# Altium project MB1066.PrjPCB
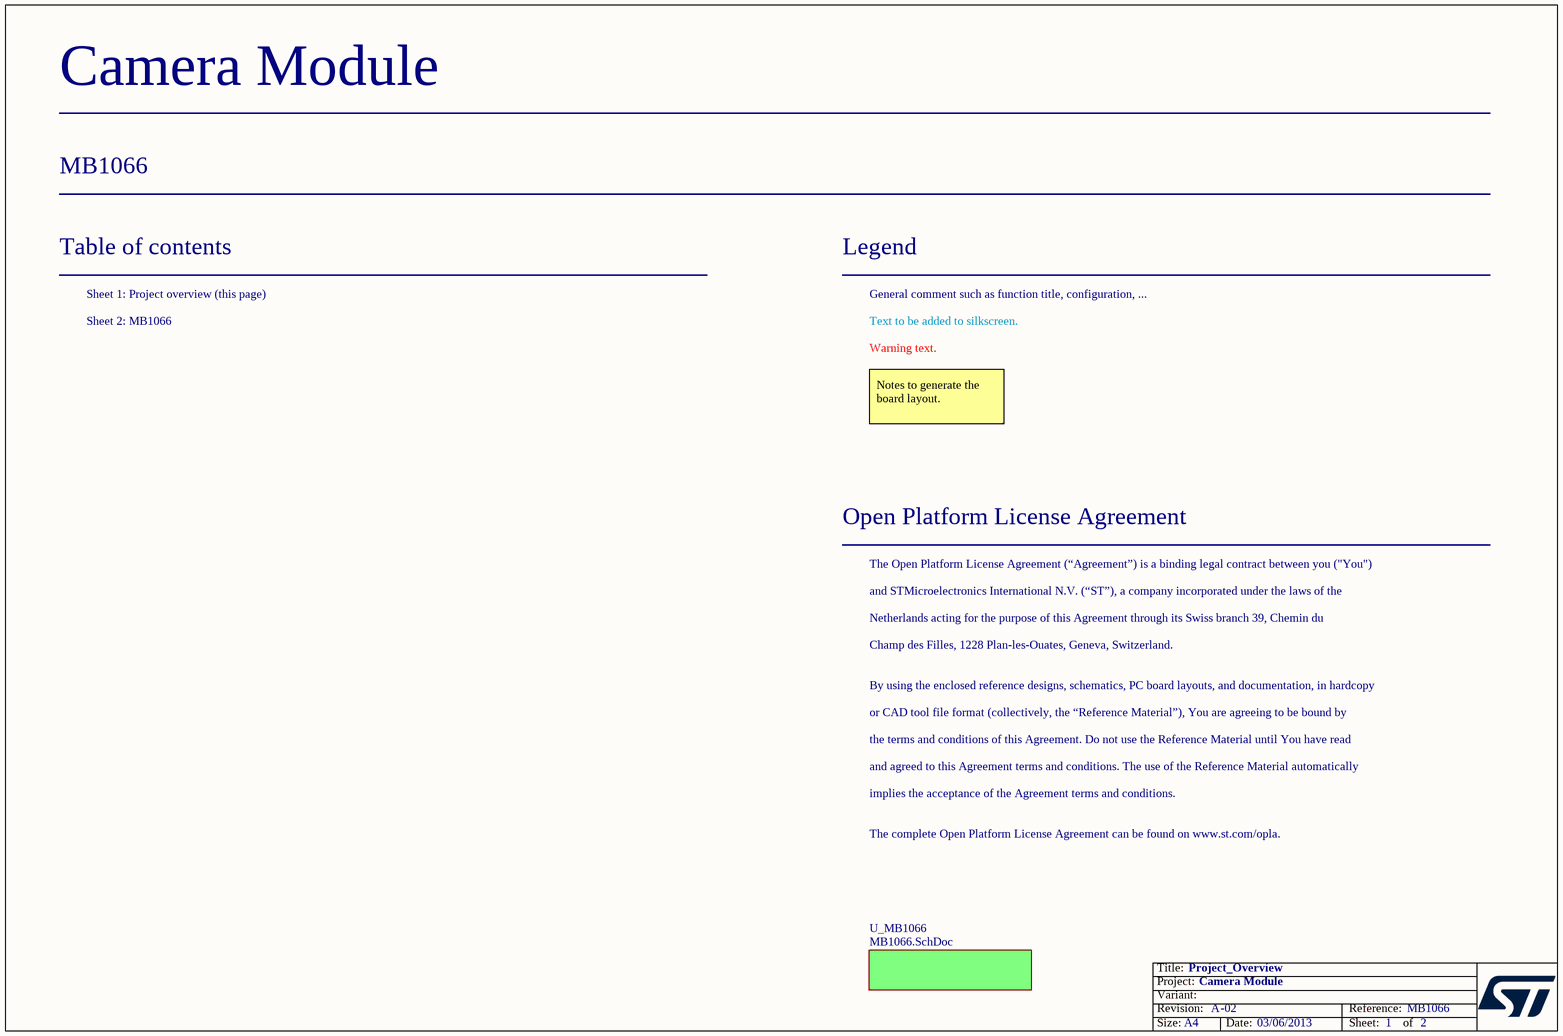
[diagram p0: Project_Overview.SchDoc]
Board_Assembly_Revision: 02; Board_Document_Date: 03/06/2013; Board_Name: Camera Module; Board_PCB_Revision: A; Board_Reference: MB1066
2 sheets, 22 parts. Net scope: global (net labels, ports and power ports of the same name join across sheets).
Board file: MB1066.PcbDoc
Sheets:
  Project_Overview.SchDoc
    U_MB1066 = MB1066.SchDoc

## Sheet Project_Overview.SchDoc: Project_Overview
size A4; Date: Not used; ApprovedBy: Not used; CheckedBy: Not used; Author: Not used; CompanyName: STMicroelectronics; DrawnBy: Not used; Engineer: Not used; Organization: Not used; Address1: Not used; Address2: Not used; Address3: Not used; Address4: Not used; DocumentNumber: 1; Revision: Not used; SheetNumber: 1; SheetTotal: 2

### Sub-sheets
U_MB1066 = MB1066.SchDoc: no entries

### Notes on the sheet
- Table of contents
- Sheet 1: Project overview (this page)
- Legend
- General comment such as function title, configuration, ...
- Sheet 2: MB1066
- Text to be added to silkscreen.
- Warning text.
- Notes to generate the board layout.
- Open Platform License Agreement
- The Open Platform License Agreement (“Agreement”) is a binding legal contract between you ("You")
- and STMicroelectronics International N.V. (“ST”), a company incorporated under the laws of the
- Netherlands acting for the purpose of this Agreement through its Swiss branch 39, Chemin du
- Champ des Filles, 1228 Plan-les-Ouates, Geneva, Switzerland.
- By using the enclosed reference designs, schematics, PC board layouts, and documentation, in hardcopy
- or CAD tool file format (collectively, the “Reference Material”), You are agreeing to be bound by
- the terms and conditions of this Agreement. Do not use the Reference Material until You have read
- and agreed to this Agreement terms and conditions. The use of the Reference Material automatically
- implies the acceptance of the Agreement terms and conditions.
- The complete Open Platform License Agreement can be found on www.st.com/opla.

## Sheet MB1066.SchDoc: MB1066 Camera Module
size A4; DocumentNumber: 2; Revision: A.2; SheetNumber: 2; SheetTotal: 2
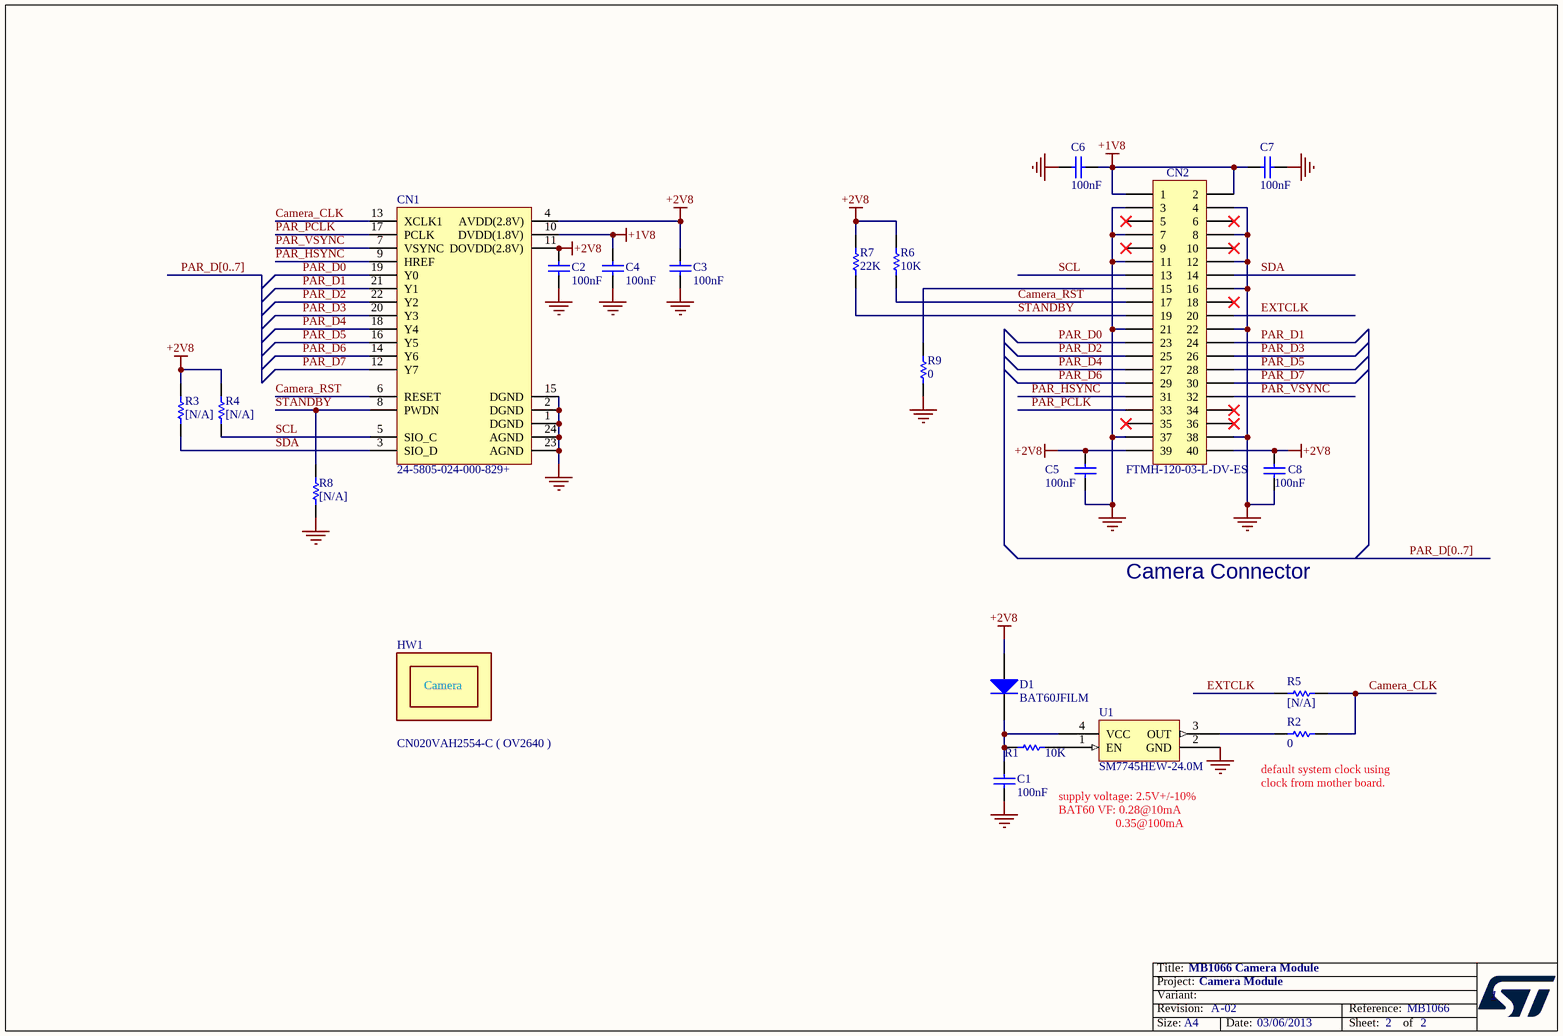
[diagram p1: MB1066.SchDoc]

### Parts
C1  100nF  [0603C]
C2  100nF  [0603C]
C3  100nF  [0603L]
C4  100nF  [0603C]
C5  100nF  [0603C]
C6  100nF  [0603C]
C7  100nF  [0603C]
C8  100nF  [0603C]
CN1  24-5805-024-000-829+  [24-5805-024-000-829]
CN2  FTMH-120-03-L-DV-ES  [FTMH-120-03-L-DV-ES]
D1  BAT60JFILM  [SOD-323]
HW1  CN020VAH2554-C ( OV2640 )  (mechanical)
R1  10K  [0603R]
R2  0  [0603R]
R3  [N/A]  [0603R]
R4  [N/A]  [0603R]
R5  [N/A]  [0603R]
R6  10K  [0603R]
R7  22K  [0603R]
R8  [N/A]  [0603R]
R9  0  [0603R]
U1  SM7745HEW-24.0M  [XTAL_5X7]

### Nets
+1V8: C4.1 C6.2 C7.1 CN1.10(DVDD(1.8V)) CN2.1 CN2.2
+2V8: C2.1 C3.1 C5.1 C8.1 CN1.4(AVDD(2.8V)) CN1.11(DOVDD(2.8V)) CN2.39 CN2.40 D1.1(A) R3.1 R4.1 R6.1 R7.1
GND: C1.2 C2.2 C3.2 C4.2 C5.2 C6.1 C7.2 C8.2 CN1.1(DGND) CN1.2(DGND) CN1.15(DGND) CN1.23(AGND) CN1.24(AGND) CN2.3 CN2.4 CN2.7 CN2.8 CN2.11 CN2.12 CN2.16 CN2.21 CN2.22 CN2.37 CN2.38 R8.1 R9.2 U1.2(GND)
Camera_CLK: CN1.13(XCLK1) R2.2 R5.2
Camera_RST: CN1.6(RESET) CN2.17 R6.2
EXTCLK: CN2.20 R5.1
PAR_D0: CN1.19(Y0) CN2.23
PAR_D1: CN1.21(Y1) CN2.24
PAR_D2: CN1.22(Y2) CN2.25
PAR_D3: CN1.20(Y3) CN2.26
PAR_D4: CN1.18(Y4) CN2.27
PAR_D5: CN1.16(Y5) CN2.28
PAR_D6: CN1.14(Y6) CN2.29
PAR_D7: CN1.12(Y7) CN2.30
PAR_HSYNC: CN1.9(HREF) CN2.31
PAR_PCLK: CN1.17(PCLK) CN2.33
PAR_VSYNC: CN1.7(VSYNC) CN2.32
SCL: CN1.5(SIO_C) CN2.13 R4.2
SDA: CN1.3(SIO_D) CN2.14 R3.2
STANDBY: CN1.8(PWDN) CN2.19 R7.2 R8.2
NetC1_1: C1.1 D1.2(K) R1.1 U1.4(VCC)
NetCN2_15: CN2.15 R9.1
NetR1_2: R1.2 U1.1(EN)
NetR2_1: R2.1 U1.3(OUT)

Not connected (* = marked no-connect by the designer): CN2 5* 6* 9* 10* 18* 34* 35* 36*

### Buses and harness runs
bus PAR_D[0..7]

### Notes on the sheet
- Camera Connector
- supply voltage: 2.5V+/-10%
  BAT60 VF: 0.28@10mA
  0.35@100mA
- (near R2) default system clock using clock from mother board.
- 1

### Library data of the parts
C1-C8 = Cap: Capacitor; Value: 10nF
CN2 = Header 20X2: 20*2Pins, 1mm_SMT, male
D1 = Diode: Default Diode; Code - JEDEC: DO-214-AB
HW1 = Camera_MODULE
R1 R4-R9 = Res1: Resistor; Value: 1K
R2 = Res1: Resistor
R3 = Res1: Resistor 10K; Value: 1K
U1 = SM7745HEV-50.0M

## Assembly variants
Default: not fitted R3 R4 R5 R8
